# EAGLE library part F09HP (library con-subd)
SUB-D
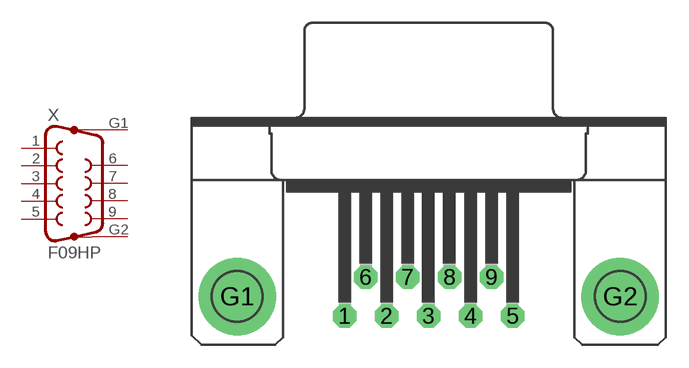
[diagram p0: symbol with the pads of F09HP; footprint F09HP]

Designator prefix X

## F09HP (OC_FARNELL: unknown; OC_NEWARK: unknown)  [F09HP]
1  1  pas
2  2  pas
3  3  pas
4  4  pas
5  5  pas
6  6  pas
7  7  pas
8  8  pas
9  9  pas
G1  G1  pas
G2  G2  pas

## Footprint F09HP (pad centres in mm)
SUB-D
drill 1.016 octagon: 1 -5.486,-1.27; 2 -2.743,-1.27; 3 0,-1.27; 4 2.743,-1.27; 5 5.486,-1.27; 6 -4.115,1.27; 7 -1.372,1.27; 8 1.372,1.27; 9 4.115,1.27
drill 3.302 pad 5.08 round: G1 -12.522,0; G2 12.522,0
